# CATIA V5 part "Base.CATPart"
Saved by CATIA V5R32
Part number: Base
Bounding box of the stored display mesh (mm): x -30 to 30, y -60 to 60, z -85 to -20
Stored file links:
  D:\PROJECTS\Project 2022\CATIA V5 6R 2022\Resources\Part Files\c12_catia_v5_6r2022_prt\c12_catia_v5-6r2022 figr_12-35\Base.CATPart
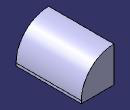
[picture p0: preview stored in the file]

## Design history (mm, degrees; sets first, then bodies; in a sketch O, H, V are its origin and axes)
Body1 (main body)
  Sketch1 on xy-plane, origin (0, 0, 0), H (1, 0, 0), V (0, 1, 0)
    line L1 (30, 60) -> (30, -60)
    line L2 (30, -60) -> (-30, -60)
    line L3 (-30, -60) -> (-30, 60)
    line L4 (-30, 60) -> (30, 60)
    length L2 = 60
    length L3 = 120
    vertical: L1 V, L3 V
    horizontal: L2 H, L4 H
    equidistance: L1 L3 O, L2 L4 O
  Pad1: profile Sketch1, direction (0, 0, -1), length 85, opposite side length -20
  Fillet1: radius 60, on edge [face of Pad1 | face of Pad1]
